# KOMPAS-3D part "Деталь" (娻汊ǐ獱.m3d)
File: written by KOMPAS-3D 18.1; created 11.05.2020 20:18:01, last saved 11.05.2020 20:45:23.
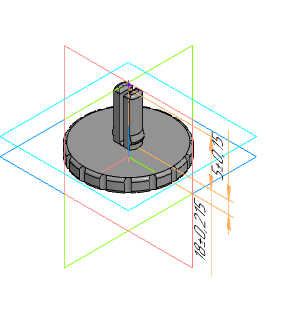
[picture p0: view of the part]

Document properties: Автор: Leha; Полное имя файла: C:\Users\Leha\Desktop\Крутилка.m3d

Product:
- Part/product: Деталь
    Масса: 0.0429811

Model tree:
1. Эскиз:1
2. Элемент выдавливания:1
     Расстояние 1 = 5
3. Эскиз:2  (with: Элемент выдавливания:1)
4. Элемент выдавливания:2
     Расстояние 1 = 18
5. Смещенная плоскость:1
     Расстояние = 6.8
6. Эскиз:3
7. Элемент выдавливания:3
     Расстояние 1 = 3
8. Фаска:1  (with: Элемент выдавливания:3)
     Угол = 75.9638; Длина 1 = 0.5; Длина 2 = 2
9. Скругление:1  (with: Элемент выдавливания:3)
     Радиус = 0.5
10. Эскиз:4  (with: Элемент выдавливания:2)
11. Элемент выдавливания:4  (with: Элемент выдавливания:1)
     Расстояние 2 = 18
12. Эскиз:5  (with: Элемент выдавливания:2)
13. Элемент выдавливания:5  (with: Элемент выдавливания:1)
     Расстояние 2 = 18
14. Скругление:2  (with: Элемент выдавливания:5)
     Радиус = 0.75
15. Скругление:3  (with: Элемент выдавливания:5, Элемент выдавливания:4, Элемент выдавливания:2)
     Радиус = 1
16. Скругление:4  (with: Элемент выдавливания:1)
     Радиус = 1
17. Эскиз:7  (with: Элемент выдавливания:1)
18. Элемент выдавливания:7
     Расстояние 2 = 5
19. Скругление:5  (with: Элемент выдавливания:1)
     Радиус = 1
20. Массив по концентрической сетке:1  (with: Элемент выдавливания:7)  (16 pattern instances)
     Шаг 2 = 360
21. Линейный размер:1  (with: Элемент выдавливания:1, Элемент выдавливания:2)
     Значение = 18
22. Линейный размер:2  (with: Элемент выдавливания:1)
     Значение = 5
23. Точка:2
     Z = 24; Координата Z = 24
24. Осевая линия:1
